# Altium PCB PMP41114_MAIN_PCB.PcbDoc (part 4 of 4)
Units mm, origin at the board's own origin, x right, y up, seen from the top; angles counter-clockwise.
Board outline 159.1 x 70 mm, 6 copper layers (Top Layer, Signal Layer 1, Signal Layer 2, Signal Layer 3, Signal Layer 4, Bottom Layer), stack 1.671 mm thick; 188 components, 146 nets, 720 pads, 326 vias.
Unrouted connection lines stored in the file: 209.
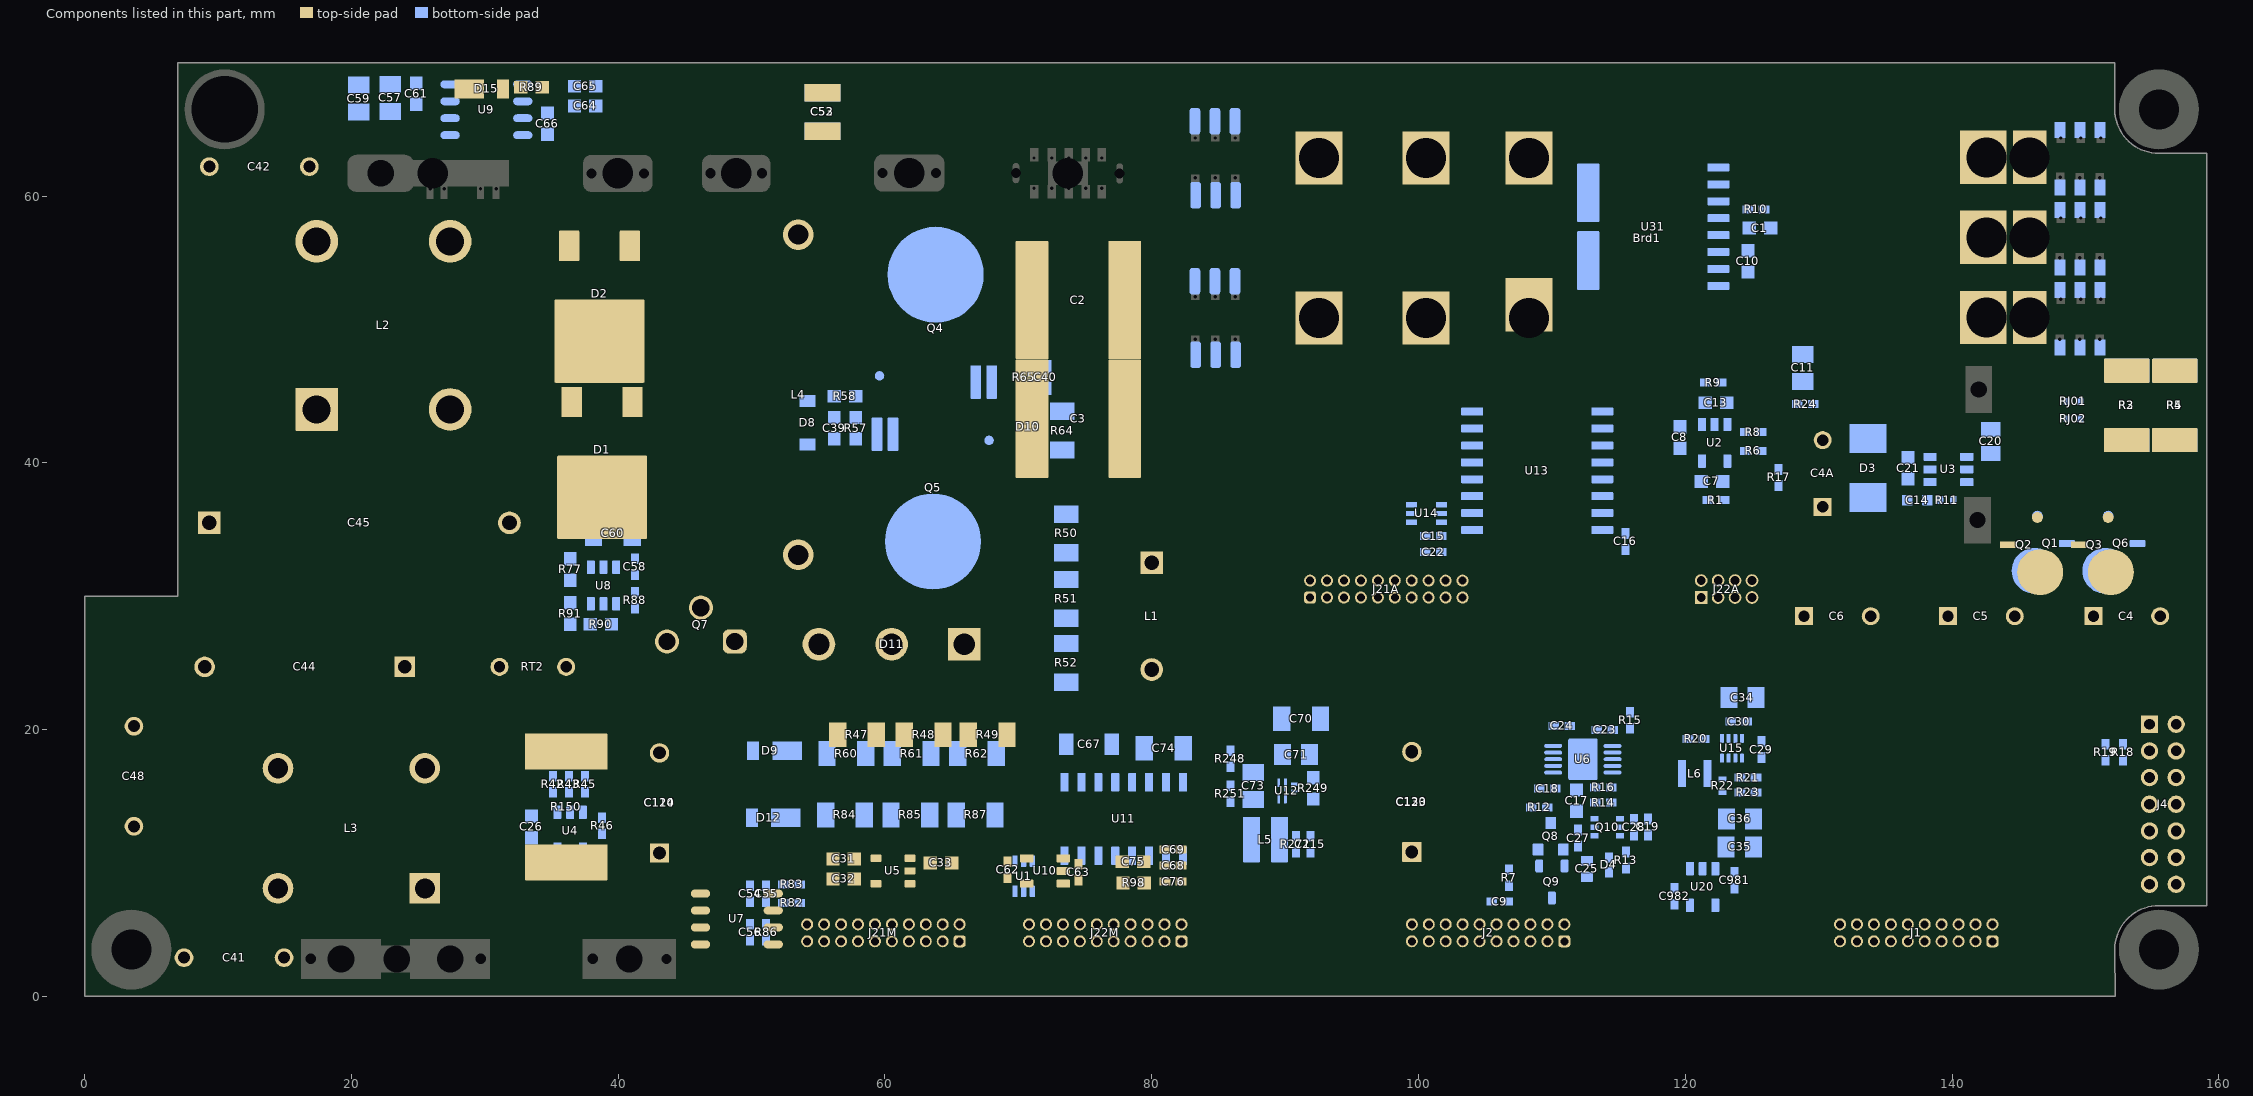
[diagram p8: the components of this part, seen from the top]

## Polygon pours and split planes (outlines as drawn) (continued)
Lout on Signal Layer 1 "SIGNAL_LAYER_1_LOUT_P439" (solid, remove dead copper, pour order 439): 11.7,7.7 13.3,9.3 20,9.3 24.8,4.5 30.4,4.5 30.4,1.6 29.5,0.7 12.9,0.7 11.7,1.9
Vbulk1 on Signal Layer 1 "SIGNAL_LAYER_1_VBULK1_P427" (solid, remove dead copper, pour order 427): 65.9,64.1 66.9,63.1 66.9,58.3 65.7,57.1 59.4,57.1 58.6,57.9 58.6,62.9 59.8,64.1
PGND on Signal Layer 1 "SIGNAL_LAYER_1_PGND_P420" (solid, remove dead copper, pour order 420): 73.4,59.8 73.975,59.225 78.475,59.225 78.7,59.45 78.7,63.925 76.225,63.925 75.775,63.475 75.775,61.425 75.175,60.825 73.55,60.825 73.4,60.675
SGND-1 on Bottom Layer "BOTTOM_LAYER_SGND-1_P561" (solid, remove dead copper, pour order 561): 144.3,69.1 147.4,69.1 147.4,48.7 147.4,47.5 144.3,47.5
PGND on Bottom Layer "BOTTOM_LAYER_PGND_P547" (solid, remove dead copper, pour order 547): 89.664,67.151 95.164,67.151 95.764,66.551 95.764,46.251 89.664,46.251
VBB on Bottom Layer "BOTTOM_LAYER_VBB_P546" (solid, remove dead copper, pour order 546): 97.4,67.3 102.9,67.3 103.5,66.7 103.5,46.4 97.4,46.4
54Vout-1 on Bottom Layer "BOTTOM_LAYER_54VOUT-1_P395" (solid, remove dead copper, pour order 395): 18 vertices, not listed, extent 128.2,10.7 157.3,38.6
PE on Bottom Layer "BOTTOM_LAYER_PE_P528" (solid, remove dead copper, pour order 528): 7.6,62.9 9,61.5 10.8,61.5 16.2,66.9 16.2,69.4 16,69.6 8.2,69.6 7.6,69
Lout on Bottom Layer "BOTTOM_LAYER_LOUT_P529" (solid, remove dead copper, pour order 529): 17.9,9.4 22.3,5 29.7,5 30.5,4.2 30.5,1.3 30.1,0.9 18.7,0.9 15.7,3.9 13.3,6.3 13.3,8.8 13.9,9.4
PE on Bottom Layer "BOTTOM_LAYER_PE_P523" (solid, remove dead copper, pour order 523): 7.2,0.5 8.2,1.5 8.2,12.4 6.7,13.9 1.5,13.9 0.6,13 0.6,2.1 0.7,2.1 2.3,0.5 0.7,2.1 2.3,0.5
ZCD on Bottom Layer "BOTTOM_LAYER_ZCD_P507" (solid, pour order 507): 47.7,65.5 36.8,65.5 34.5,63.2 34.5,60.3 34.6,60.2 34.8,60.2 34.9,60.3 34.9,63.1 36.7,64.9 46.7,64.9 46.8,65
VBB on Bottom Layer "BOTTOM_LAYER_VBB_P500" (solid, remove dead copper, pour order 500): 58.3,25.7 58.3,38.2 68.4,38.2 68.7,37.9 68.7,30 67.9,29.2 63.1,29.2 62.4,28.5 62.4,25.5 61.5,24.6 59.4,24.6
NetBrd1_S8 on Bottom Layer "BOTTOM_LAYER_NETBRD1_S8_P491" (solid, remove dead copper, pour order 491): 143.7,66.21 143.8,66.11 143.8,45.91 142.5,44.61 140.3,44.61 139.7,45.21 139.7,66.01 139.9,66.21
Line on Bottom Layer "BOTTOM_LAYER_LINE_P431" (solid, remove dead copper, pour order 431): 23 vertices, not listed, extent 25.6,29.7 55.1,57.9
NetC41_2 on Bottom Layer "BOTTOM_LAYER_NETC41_2_P465" (solid, remove dead copper, pour order 465): 8.1,17.8 12.1,13.8 19.1,13.8 19.1,52.7 18.1,53.7 10.3,53.7 8.1,51.5
NetC44_1 on Bottom Layer "BOTTOM_LAYER_NETC44_1_P459" (solid, remove dead copper, pour order 459): 24.088,46.9 28.156,46.9 29.4,45.573 29.4,29.4 27,27 27,13.6 25.9,12.5 23.4,12.5 22.2,13.7 22.2,43.843
Nout on Bottom Layer "BOTTOM_LAYER_NOUT_P450" (solid, remove dead copper, pour order 450): 43,8 46.4,8 46.6,7.8 46.6,6.1 46.3,5.8 42.8,5.8 42.5,6.1 42.5,7.5
N on Bottom Layer "BOTTOM_LAYER_N_P445" (solid, remove dead copper, pour order 445): 37.3,4.3 38.5,5.5 45.7,5.5 46.7,4.5 46.7,1.2 46.3,0.8 37.9,0.8 37.3,1.4
PGND on Bottom Layer "BOTTOM_LAYER_PGND_P444" (solid, remove dead copper, pour order 444): 39.6,8.3 41.3,10 43.8,10 43.8,11.6 42.4,13 40.8,13 38.1,10.3 33.6,10.3 33,9.7 33,9 33.7,8.3
Vbulk1 on Bottom Layer "BOTTOM_LAYER_VBULK1_P432" (solid, remove dead copper, pour order 432): 52.7,68.9 53.2,69.4 66,69.4 66.9,68.5 66.9,60.4 69.7,57.6 69.7,49.8 69.4,49.5 58.7,49.5 58.1,50.1 58.1,66.4 57.4,67.1 53.2,67.1 52.7,67.6
ZCD on Bottom Layer "BOTTOM_LAYER_ZCD_P424" (solid, remove dead copper, pour order 424): 46.1,60.9 46.7,60.3 55.8,60.3 56.7,61.2 56.7,65.5 46.7,65.5 46.1,64.9
Vbulk on Bottom Layer "BOTTOM_LAYER_VBULK_P421" (solid, remove dead copper, pour order 421): 67.1,47.4 67.3,47.2 67.3,44.2 67.5,44 68.1,44 68.4,43.7 68.4,40.9 60.3,40.9 60.2,41 60.2,43.8 60.1,43.9 59,43.9 58.7,44.2 58.7,47.4
Vbulk1 on Bottom Layer "BOTTOM_LAYER_VBULK1_P419" (solid, remove dead copper, pour order 419): 65.9,64.1 66.9,63.1 66.9,59.9 68.9,57.9 68.9,49.9 68.5,49.5 58.6,49.5 58.6,62.9 59.8,64.1
MID-1 on Bottom Layer "BOTTOM_LAYER_MID-1_P409" (solid, remove dead copper, pour order 409): 105.899,57.715 113.5,57.715 113.5,50.455 109.67,47 106,47 105.199,47.801 105.199,57.015
MID-2 on Bottom Layer "BOTTOM_LAYER_MID-2_P408" (solid, remove dead copper, pour order 408): 105.8,67.4 113.8,67.4 113.8,58 105.9,58 105.1,58.8 105.1,66.7
SGND on Bottom Layer "BOTTOM_LAYER_SGND_P398" (solid, remove dead copper, pour order 398): 150.1,47.786 151.857,47.786 151.857,62.1 158.5,62.1 158.5,45.4 157.9,44.8 151,44.8 150.1,45.7
SGND-1 on Bottom Layer "BOTTOM_LAYER_SGND-1_P397" (solid, remove dead copper, pour order 397): 151.7,40.7 151.1,41.3 151.1,43.3 151.7,43.9 158.2,43.9 158.5,43.6 158.5,40.7 151.8,40.7
54Vout on Bottom Layer "BOTTOM_LAYER_54VOUT_P396" (solid, remove dead copper, pour order 396): 144.3,35.5 157.6,35.5 158.4,36.3 158.4,39.7 157.8,40.3 144.8,40.3 144.1,39.6 144.1,35.7
NetBrd1_S8 on Bottom Layer "BOTTOM_LAYER_NETBRD1_S8_P393" (solid, remove dead copper, pour order 393): 143.7,69.2 143.9,69 143.9,44.2 143.2,43.5 134.6,43.5 130.8,43.5 127.7,46.6 127.7,66.6 130.3,69.2
PGND on Bottom Layer "BOTTOM_LAYER_PGND_P248" (solid, remove dead copper, pour order 248): 73.391,59.807 73.941,59.257 78.491,59.257 78.691,59.457 78.691,63.932 76.216,63.932 75.766,63.482 75.766,61.432 75.459,61.125 73.7,61.125 73.391,60.816
ZCD on Bottom Layer "ZCD" (solid, remove dead copper, pour order 388): 21 vertices, not listed, extent 30.75,58.75 39.75,69.25
Neutral on Bottom Layer "Neutral" (solid, remove dead copper, pour order 390): 20,66.75 19.75,66.5 19.75,65.5 20,65.25 26.5,65.25 26.75,65.5 28,65.5 28.25,65.75 28.25,66 28,66.25 26,66.25 25.25,67 20,67 19.75,66.75
VBB on Signal Layer 4 "SIGNAL_LAYER_4_VBB_P496" (solid, remove dead copper, pour order 496): 70.7,49.1 79.8,40 100,40 104.8,44.8 104.8,54.5 104.8,65.3 102.8,67.3 81.32,67.3 81.32,59.72 80.1,58.5 71.9,58.5 70.7,57.3 70.7,57.2
12VSB on Signal Layer 4 "Signal Layer 4-12VSB" (solid, remove dead copper, pour order 574): 116.9,1.5 152.6,1.5 158.5,7.4 158.5,22.3 129.3,22.3 125.4,26.2 125.4,44.1 123.147,44.1 116.9,37.767 116.9,23.231
AGND on Signal Layer 4 "SIGNAL_LAYER_4_AGND_P569" (solid, remove dead copper, pour order 569): 98,3.5 98,6.2 99.2,7.4 102.6,7.4 110.198,14.998 110.198,18.121 113,20.924 113,37.479 123.8,48.279 123.8,57.4 125,57.4 125,47.834 115.4,38.234 115.4,12.4 106.5,3.5
ZCD on Signal Layer 4 "SIGNAL_LAYER_4_ZCD_P566" (solid, remove dead copper, pour order 566): 46.275,60.725 46.675,60.325 51.075,60.325 51.375,60.625 51.375,64.025 49.475,65.925 35.075,65.925 32.775,63.625 32.775,59.725 33.375,59.125 34.175,59.125 34.175,64.225 35.475,65.525 45.875,65.525 46.275,65.125
SGND-1 on Signal Layer 4 "SIGNAL_LAYER_4_SGND-1_P559" (solid, remove dead copper, pour order 559): 126.1,65.3 126.1,26.5 129.5,23.1 158.5,23.1 158.5,69.2 130,69.2
PE on Signal Layer 4 "SIGNAL_LAYER_4_PE_P534" (solid, remove dead copper, pour order 534): 7.6,62.9 9,61.5 10.8,61.5 16.2,66.9 16.2,69.4 16,69.6 8.2,69.6 7.6,69
Lout on Signal Layer 4 "SIGNAL_LAYER_4_LOUT_P525" (solid, remove dead copper, pour order 525): 11.7,7.7 13.3,9.3 20,9.3 24.8,4.5 30.4,4.5 30.4,1.6 29.5,0.7 12.9,0.7 11.7,1.9
PE on Signal Layer 4 "SIGNAL_LAYER_4_PE_P524" (solid, remove dead copper, pour order 524): 7.2,0.5 8.2,1.5 8.2,11.3 5.8,13.7 1.3,13.7 0.6,13 0.6,2.1 0.7,2.1 2.3,0.5 0.7,2.1 2.3,0.5
Vbulk on Signal Layer 4 "SIGNAL_LAYER_4_VBULK_P470" (solid, remove dead copper, pour order 470): 41.4,16.6 41.4,18.1 56.1,32.8 56.1,45.1 59.9,48.9 70.2,48.9 101.1,18 101.1,16.4 100.4,15.7 42.3,15.7
ZCD on Signal Layer 4 "SIGNAL_LAYER_4_ZCD_P425" (solid, remove dead copper, pour order 425): 19 vertices, not listed, extent 33.1,19.6 55.2,65
Vbulk1 on Signal Layer 4 "SIGNAL_LAYER_4_VBULK1_P480" (solid, remove dead copper, pour order 480): 58.5,63.4 66.7,63.4 66.7,58.1 66.2,57.6 59.5,57.6 58.5,58.6
Line on Signal Layer 4 "SIGNAL_LAYER_4_LINE_P475" (solid, remove dead copper, pour order 475): 25.6,57 26.5,57.9 28.4,57.9 33,53.3 33,40.6 33,34.9 32.4,34.3 30.8,34.3 29.8,35.3 29.8,45.9 25.6,50.1
NetC41_2 on Signal Layer 4 "SIGNAL_LAYER_4_NETC41_2_P466" (solid, remove dead copper, pour order 466): 8.1,19.1 12,15.2 17.1,15.2 19.9,18 19.9,51.9 18.1,53.7 13.5,53.7 8.1,48.3
NetC44_1 on Signal Layer 4 "SIGNAL_LAYER_4_NETC44_1_P458" (solid, remove dead copper, pour order 458): 22.95,46.9 27.956,46.9 29.7,45.04 29.7,26.3 28.9,25.5 28.9,15.5 25.9,12.5 23.4,12.5 21.3,14.6 21.3,44.229
N on Signal Layer 4 "SIGNAL_LAYER_4_N_P446" (solid, remove dead copper, pour order 446): 37.3,4.3 38.3,5.3 45.9,5.3 46.7,4.5 46.7,1.2 46.3,0.8 37.9,0.8 37.3,1.4
Nout on Signal Layer 4 "SIGNAL_LAYER_4_NOUT_P438" (solid, remove dead copper, pour order 438): 24.7,10.6 29.3,10.6 31.9,8 46.4,8 47.1,7.3 47.1,6.2 46.4,5.5 25,5.5 23,7.5 23,8.9
PGND on Signal Layer 4 "SIGNAL_LAYER_4_PGND_P429" (solid, remove dead copper, pour order 429): 33.4,13.8 98.6,13.8 100.2,12.2 100.2,10.1 99.5,9.4 83.997,9.4 83.4,8.949 83.4,7.3 82.8,6.7 49.1,6.7 47.1,8.7 33.4,8.7
PGND on Signal Layer 4 "SIGNAL_LAYER_4_PGND_P222" (solid, remove dead copper, pour order 222): 76.3,64 78.5,64 78.75,63.75 78.75,59.5 78.5,59.25 73.95,59.25 73.4,59.8 73.4,60.675 73.55,60.825 75.175,60.825 75.775,61.425 75.775,63.475
12VS on Signal Layer 3 "Signal Layer 3-12VS" (solid, remove dead copper, pour order 573): 17 vertices, not listed, extent 92.4,0.8 158.5,45.6
SGND-1 on Signal Layer 3 "SIGNAL_LAYER_3_SGND-1_P563" (solid, remove dead copper, pour order 563): 127.9,69.2 127.9,23.8 129.7,22 158.5,22 158.5,69.2
VBB on Signal Layer 3 "SIGNAL_LAYER_3_VBB_P545" (solid, remove dead copper, pour order 545): 97.4,67.3 102.9,67.3 104.5,65.7 104.5,54.8 104.5,46.7 104.2,46.4 98.835,46.4 97.4,47.834
SGND-1 on Signal Layer 3 "SIGNAL_LAYER_3_SGND-1_P542" (solid, remove dead copper, pour order 542): 144.3,69.1 144.3,41.856 147.456,38.7 158.6,38.7 158.6,44.3 151.2,44.3 151.2,48.7 147.4,48.7 147.4,69.1
PE on Signal Layer 3 "SIGNAL_LAYER_3_PE_P533" (solid, remove dead copper, pour order 533): 7.6,62.9 9,61.5 10.8,61.5 16.2,66.9 16.2,69.4 16,69.6 8.2,69.6 7.6,69
Lout on Signal Layer 3 "SIGNAL_LAYER_3_LOUT_P527" (solid, remove dead copper, pour order 527): 11.7,7.7 13.3,9.3 20,9.3 24.8,4.5 30.4,4.5 30.4,1.6 29.5,0.7 12.9,0.7 11.7,1.9
PE on Signal Layer 3 "SIGNAL_LAYER_3_PE_P521" (solid, remove dead copper, pour order 521): 7.2,0.5 8.2,1.5 8.2,12.4 6.7,13.9 1.5,13.9 0.6,13 0.6,2.1 0.7,2.1 2.3,0.5 0.7,2.1 2.3,0.5
ZCD on Signal Layer 3 "SIGNAL_LAYER_3_ZCD_P510" (solid, remove dead copper, pour order 510): 46.3,60.7 46.7,60.3 51.1,60.3 51.4,60.6 51.4,64 49.5,65.9 35.1,65.9 32.8,63.6 32.8,59.7 33.4,59.1 34.2,59.1 34.2,64.2 35.5,65.5 45.9,65.5 46.3,65.1
PGND on Signal Layer 3 "SIGNAL_LAYER_3_PGND_P508" (solid, remove dead copper, pour order 508): 43.958,27.5 45.937,25.9 48.9,25.9 52.3,22.5 74.6,22.5 74.6,6.5 63.6,6.5 49.5,20.6 42.5,20.6 40.7,22.4 40.7,26.1 42.1,27.5
NetD11_1 on Signal Layer 3 "SIGNAL_LAYER_3_NETD11_1_P499" (solid, remove dead copper, pour order 499): 45.3,30.3 45.6,30.6 66.2,30.6 67.8,29 67.8,23.5 52.8,23.5 51.5,24.8 51.5,27.8 50.4,28.9 47.557,28.9 46.957,28.2 45.6,28.2 45.3,28.5
PGND on Signal Layer 3 "SIGNAL_LAYER_3_NONET_P484" (solid, remove dead copper, pour order 498): 96.1,69.4 96.1,53.5 96.1,47.377 104.7,38.777 104.7,23.5 102.8,21.6 102.8,12.7 99.9,9.8 72.7,9.8 70.3,12.2 70.3,63.8 75.9,69.4
PGND on Signal Layer 3 "SIGNAL_LAYER_3_PGND_P487" (solid, remove dead copper, pour order 487): 33.8,8.9 46,8.9 46.8,9.7 46.8,11 46.2,11.6 35.5,11.6 33.6,9.7 33.6,9.1
SWNODE on Signal Layer 3 "SIGNAL_LAYER_3_SWNODE_P482" (solid, remove dead copper, pour order 482): 43,63.2 44.2,62 44.2,60.5 45.1,59.6 55.4,59.6 57.6,57.4 57.6,53.9 57.5,53.9 56.8,53.2 38.6,53.2 37.3,54.5 37.3,62.9 37.6,63.2
Line on Signal Layer 3 "SIGNAL_LAYER_3_LINE_P476" (solid, remove dead copper, pour order 476): 23 vertices, not listed, extent 25.6,31.9 54.8,57.9
Neutral on Signal Layer 3 "SIGNAL_LAYER_3_NEUTRAL_P474" (solid, remove dead copper, pour order 474): 8.1,48.5 17.5,48.5 24.5,55.5 24.5,65.1 23.6,66 18,66 8.1,56.1
NetC41_2 on Signal Layer 3 "SIGNAL_LAYER_3_NETC41_2_P457" (solid, remove dead copper, pour order 457): 8.1,17.8 12.1,13.8 19.1,13.8 19.9,14.6 19.9,47 8.1,47
NetC44_1 on Signal Layer 3 "SIGNAL_LAYER_3_NETC44_1_P468" (solid, remove dead copper, pour order 468): 24.088,46.9 28.156,46.9 29.7,45.253 29.7,26.3 28.9,25.5 28.9,17.3 27.4,15.8 22.8,15.8 21.3,17.3 21.3,42.386
N on Signal Layer 3 "SIGNAL_LAYER_3_N_P456" (solid, remove dead copper, pour order 456): 37.3,4.3 38.3,5.3 45.9,5.3 46.7,4.5 46.7,1.2 46.3,0.8 37.9,0.8 37.3,1.4
Nout on Signal Layer 3 "SIGNAL_LAYER_3_NOUT_P447" (solid, remove dead copper, pour order 447): 24.7,10.6 29.3,10.6 31.9,8 46.4,8 47.1,7.3 47.1,6.2 46.4,5.5 25,5.5 23,7.5 23,8.9
PGND on Signal Layer 3 "SIGNAL_LAYER_3_PGND_P441" (solid, remove dead copper, pour order 441): 73.391,59.807 73.941,59.257 78.491,59.257 78.691,59.457 78.691,63.932 76.216,63.932 75.766,63.482 75.766,61.432 75.166,60.832 73.541,60.832 73.391,60.682
54Vout on Signal Layer 2 "SIGNAL_LAYER_2_54VOUT_P576" (solid, remove dead copper, pour order 576): 142.988,34.5 142.988,37.412 148.047,42.47 158.362,42.321 158.362,34.5
54Vout-1 on Signal Layer 2 "SIGNAL_LAYER_2_54VOUT-1_P565" (solid, remove dead copper, pour order 565): 126.5,39.6 143.6,39.6 148.7,34.5 158.1,34.5 158.1,22.1 155.7,19.7 129.4,19.7 125.5,23.6 125.5,38.6
SGND on Signal Layer 2 "Signal Layer 2-SGND" (solid, remove dead copper, pour order 572): 18 vertices, not listed, extent 92.4,0.8 158.5,63.2
NetBrd1_S8 on Signal Layer 2 "SIGNAL_LAYER_2_NETBRD1_S8_P557" (solid, remove dead copper, pour order 557): 147,69.2 147,40.3 126.9,40.3 124.8,42.4 124.8,63.6 130.4,69.2
VBB on Signal Layer 2 "SIGNAL_LAYER_2_VBB_P411" (solid, remove dead copper, pour order 411): 97.4,67.3 102.9,67.3 104.5,65.7 104.5,54.8 104.5,46.7 104.2,46.4 97.4,46.4
PGND on Signal Layer 2 "SIGNAL_LAYER_2_PGND_P544" (solid, remove dead copper, pour order 544): 90,67.3 94.883,67.3 96.483,65.7 96.483,54.8 96.483,46.7 96.183,46.4 90.96,46.4 90,47.36
PE on Signal Layer 2 "SIGNAL_LAYER_2_PE_P532" (solid, remove dead copper, pour order 532): 7.6,62.9 9,61.5 10.8,61.5 16.2,66.9 16.2,69.4 16,69.6 8.2,69.6 7.6,69
PE on Signal Layer 2 "SIGNAL_LAYER_2_PE_P522" (solid, remove dead copper, pour order 522): 7.2,0.5 8.2,1.5 8.2,12.4 6.7,13.9 1.5,13.9 0.6,13 0.6,2.1 0.7,2.1 2.3,0.5 0.7,2.1 2.3,0.5
SGND on Signal Layer 2 "SIGNAL_LAYER_2_SGND_P516" (solid, remove dead copper, pour order 516): 114.2,14.8 117.3,14.8 127.5,4.6 131.9,4.6 132.1,4.4 132.1,2.3 130.6,0.8 113.6,0.8 112.9,1.5 112.9,13.5
PGND on Signal Layer 2 "SIGNAL_LAYER_2_PGND_P513" (solid, remove dead copper, pour order 513): 89.4,10.6 89.4,18.4 95.1,24.1 95.1,31.5 100.9,31.5 100.9,10.8 99.8,9.7 90.3,9.7
SGND on Signal Layer 2 "SIGNAL_LAYER_2_SGND_P511" (solid, remove dead copper, pour order 511): 151.5,62.1 158,62.1 158,44.997 157.503,44.5 151.5,44.5
Vbulk1 on Signal Layer 2 "SIGNAL_LAYER_2_VBULK1_P502" (solid, remove dead copper, pour order 502): 65.9,64.1 66.9,63.1 66.9,58.3 65.7,57.1 59.4,57.1 58.6,57.9 58.6,62.9 59.8,64.1
PGND on Signal Layer 2 "SIGNAL_LAYER_2_PGND_P481" (solid, remove dead copper, pour order 481): 33.8,8.9 44.2,8.9 44.6,9.3 44.6,11.2 44.2,11.6 35.5,11.6 33.6,9.7 33.6,9.1
ZCD on Signal Layer 2 "SIGNAL_LAYER_2_ZCD_P478" (solid, remove dead copper, pour order 478): 22 vertices, not listed, extent 34.6,55.4 51.6,69.2
SWNODE on Signal Layer 2 "SIGNAL_LAYER_2_SWNODE_P426" (solid, remove dead copper, pour order 426): 43,63.2 44.2,62 44.2,60.5 45.1,59.6 55.4,59.6 56.7,58.3 56.7,56.2 55.9,55.4 42.6,55.4 37.3,60.7 37.3,62.9 37.6,63.2
Vbulk on Signal Layer 2 "SIGNAL_LAYER_2_VBULK_P471" (solid, remove dead copper, pour order 471): 39.6,49 42.7,52.1 67.9,52.1 69.9,50.1 69.9,37.3 66.5,33.9 66.5,19.6 62.8,15.9 42.9,15.9 39.6,19.2
NetC41_2 on Signal Layer 2 "SIGNAL_LAYER_2_NETC41_2_P463" (solid, remove dead copper, pour order 463): 19.3,45.6 19.6,45.3 19.5,45.2 19.5,10.9 19.3,10.7 12.5,10.7 11.9,11.3 11.9,31.2 12.1,31.2 14.3,33.4 14.3,44 15.9,45.6
Neutral on Signal Layer 2 "SIGNAL_LAYER_2_NEUTRAL_P462" (solid, remove dead copper, pour order 462): 8.1,33.7 8.2,33.6 12.9,33.6 13,33.7 13,44 24.5,55.5 24.5,65.1 23.6,66 18,66 8.1,56.1
NetC44_1 on Signal Layer 2 "SIGNAL_LAYER_2_NETC44_1_P460" (solid, remove dead copper, pour order 460): 24.088,46.9 28.156,46.9 29.7,45.253 29.7,26.3 28.9,25.5 28.9,15.5 25.9,12.5 23.4,12.5 21.3,14.6 21.3,42.386
N on Signal Layer 2 "SIGNAL_LAYER_2_N_P448" (solid, remove dead copper, pour order 448): 37.3,4.3 38.3,5.3 45.9,5.3 46.7,4.5 46.7,1.2 46.3,0.8 37.9,0.8 37.3,1.4
Nout on Signal Layer 2 "SIGNAL_LAYER_2_NOUT_P440" (solid, remove dead copper, pour order 440): 23.3,11.4 28.5,11.4 31.9,8 46.4,8 47.1,7.3 47.1,6.2 46.4,5.5 25.3,5.5 22.5,8.3 22.5,10.6
Lout on Signal Layer 2 "SIGNAL_LAYER_2_LOUT_P434" (solid, remove dead copper, pour order 434): 11.7,7.7 13.3,9.3 20,9.3 24.8,4.5 30.4,4.5 30.4,1.6 29.5,0.7 12.9,0.7 11.7,1.9
PGND on Signal Layer 2 "SIGNAL_LAYER_2_PGND_P234" (solid, remove dead copper, pour order 234): 73.4,59.25 78.6,59.25 78.6,63.925 76.225,63.925 75.775,63.475 75.775,61.425 75.175,60.825 73.55,60.825 73.4,60.675

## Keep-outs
Top Layer:
  lines w0.254: 83.5,48.2 85.8,48.2 ; 83.7,53.6 86,53.6
Signal Layer 4:
  lines w0.254: 78.784,31.3 78.784,33.7 81.154,33.7 81.154,31.3 78.784,31.3
Keep-Out Layer:
  text ".Layer_Name" at -10.544,-45.406 h1.52

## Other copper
Top Layer:
  pour cut-out: 58.515,26.4 ccw(c60.5,26.4) 60.5,24.415 ccw(c60.5,26.4) 62.485,26.4 ccw(c60.5,26.4) 60.5,28.385 ccw(c60.5,26.4)
Signal Layer 1:
  pour cut-out: 99.454,17.025 cw(c99.454,18.329) 98.151,18.329 cw(c99.454,18.329) 99.454,19.633 cw(c99.454,18.329) 100.758,18.329 cw(c99.454,18.329)
  pour cut-out: 64.181,26.4 ccw(c65.95,26.4) 65.95,24.631 ccw(c65.95,26.4) 67.719,26.4 ccw(c65.95,26.4) 65.95,28.169 ccw(c65.95,26.4)
  pour cut-out: 53.281,26.4 ccw(c55.05,26.4) 55.05,24.631 ccw(c55.05,26.4) 56.819,26.4 ccw(c55.05,26.4) 55.05,28.169 ccw(c55.05,26.4)
  pour cut-out: 79.954,23.175 cw(c79.954,24.479) 78.651,24.479 cw(c79.954,24.479) 79.954,25.783 cw(c79.954,24.479) 81.258,24.479 cw(c79.954,24.479)
  pour cut-out: 58.731,26.4 ccw(c60.5,26.4) 60.5,24.631 ccw(c60.5,26.4) 62.269,26.4 ccw(c60.5,26.4) 60.5,28.169 ccw(c60.5,26.4)
  pour cut-out: 53.2,29.094 cw(c53.2,30.4) 51.894,30.4 cw(c53.2,30.4) 53.2,31.706 cw(c53.2,30.4) 54.506,30.4 cw(c53.2,30.4)
  pour cut-out: 52.068,33.1 ccw(c53.5,33.1) 53.5,31.668 ccw(c53.5,33.1) 54.932,33.1 ccw(c53.5,33.1) 53.5,34.532 ccw(c53.5,33.1)
  pour cut-out: 55.825,40.263 cw(c55.825,40.675) 55.413,40.675 cw(c55.825,40.675) 55.825,41.087 cw(c55.825,40.675) 56.237,40.675 cw(c55.825,40.675)
  pour cut-out: 36.054,23.375 cw(c36.054,24.679) 34.751,24.679 cw(c36.054,24.679) 36.054,25.983 cw(c36.054,24.679) 37.358,24.679 cw(c36.054,24.679)
  pour cut-out: 46.202,27.853 cw(c46.202,29.157) 44.898,29.157 cw(c46.202,29.157) 46.202,30.461 cw(c46.202,29.157) 47.506,29.157 cw(c46.202,29.157)
  pour cut-out: 82.54,65.78 87.04,65.78 87.04,60.08 82.54,60.08
  pour cut-out: 82.54,53.65 87.04,53.65 87.04,47.95 82.54,47.95
  pour cut-out: 134.08,28.76 139.774,34.454 140.57,34.449 140.57,34.18 139.8,34.18 134.38,28.76
  pour cut-out: 143.002,37.402 151.474,45.874 152.074,45.87 152.075,45.6 151.5,45.6 143.302,37.402
  pour cut-out: 71.6,48.5 71.6,54.3 72.2,54.9 73.2,54.9 73.7,54.4 73.7,48.5
  pour cut-out: 61,38.5 67.2,38.5 67.8,37.9 67.8,35.7 67.1,35 61.1,35 60.4,35.7 60.4,37.9
  pour cut-out: 61,44.9 67.2,44.9 67.8,44.3 67.8,43.3 67.3,42.8 60.9,42.8 60.4,43.3 60.4,44.3
  pour cut-out: 44.4,10.1 44.4,9.7 85.95,9.7 89.915,5.961 90.283,6.129 86.209,10.1
  pour cut-out: 80.655,64.205 80.655,64.805 80.555,64.905 79.955,64.905 79.855,64.805 79.855,64.205 79.955,64.105 80.555,64.105
  pour cut-out: 102.8,30.45 103.9,30.45 103.9,29.35 102.8,29.35
  pour cut-out: 102.8,30.45 103.9,30.45 103.9,29.35 102.8,29.35
  pour cut-out: 94.3,20.5 94.3,21.1 94.2,21.2 93.6,21.2 93.5,21.1 93.5,20.5 93.6,20.4 94.2,20.4
  pour cut-out: 87.3,18.6 87.3,19.2 87.2,19.3 86.6,19.3 86.5,19.2 86.5,18.6 86.6,18.5 87.2,18.5
  pour cut-out: 100.173,29.667 100.173,31.567 99.852,31.888 95.394,31.888 95.094,31.588 95.094,29.6 95.394,29.3 99.806,29.3
  pour cut-out: 70.9,10.8 70.9,11.4 70.8,11.5 70.2,11.5 70.1,11.4 70.1,10.8 70.2,10.7 70.8,10.7
Signal Layer 2:
  pour cut-out: 97.731,18.3 ccw(c99.5,18.3) 99.5,16.531 ccw(c99.5,18.3) 101.269,18.3 ccw(c99.5,18.3) 99.5,20.069 ccw(c99.5,18.3)
  pour cut-out: 52.068,33.1 ccw(c53.5,33.1) 53.5,31.668 ccw(c53.5,33.1) 54.932,33.1 ccw(c53.5,33.1) 53.5,34.532 ccw(c53.5,33.1)
  pour cut-out: 53.234,26.481 ccw(c55.003,26.481) 55.003,24.712 ccw(c55.003,26.481) 56.773,26.481 ccw(c55.003,26.481) 55.003,28.25 ccw(c55.003,26.481)
  pour cut-out: 53.2,29.094 cw(c53.2,30.4) 51.894,30.4 cw(c53.2,30.4) 53.2,31.706 cw(c53.2,30.4) 54.506,30.4 cw(c53.2,30.4)
  pour cut-out: 41.388,25.371 cw(c41.388,26.677) 40.082,26.677 cw(c41.388,26.677) 41.388,27.983 cw(c41.388,26.677) 42.694,26.677 cw(c41.388,26.677)
  pour cut-out: 40.4,25.594 cw(c40.4,26.9) 39.094,26.9 cw(c40.4,26.9) 40.4,28.206 cw(c40.4,26.9) 41.706,26.9 cw(c40.4,26.9)
  pour cut-out: 48.74,25.294 cw(c48.74,26.6) 47.434,26.6 cw(c48.74,26.6) 48.74,27.906 cw(c48.74,26.6) 50.046,26.6 cw(c48.74,26.6)
  pour cut-out: 43.66,25.294 cw(c43.66,26.6) 42.354,26.6 cw(c43.66,26.6) 43.66,27.906 cw(c43.66,26.6) 44.966,26.6 cw(c43.66,26.6)
  pour cut-out: 46.2,27.834 cw(c46.2,29.14) 44.894,29.14 cw(c46.2,29.14) 46.2,30.446 cw(c46.2,29.14) 47.506,29.14 cw(c46.2,29.14)
  pour cut-out: 61,38.5 67.2,38.5 67.8,37.9 67.8,35.7 67.1,35 61.1,35 60.4,35.7 60.4,37.9
  pour cut-out: 67.5,27.9 67.3,28.1 64.6,28.1 64.2,27.7 64.2,25.1 64.6,24.7 67.5,24.7
  pour cut-out: 94.3,20.5 94.3,21.1 94.2,21.2 93.6,21.2 93.5,21.1 93.5,20.5 93.6,20.4 94.2,20.4
Signal Layer 3:
  pour cut-out: 99.454,16.975 cw(c99.454,18.279) 98.151,18.279 cw(c99.454,18.279) 99.454,19.583 cw(c99.454,18.279) 100.758,18.279 cw(c99.454,18.279)
  pour cut-out: 79.954,23.175 cw(c79.954,24.479) 78.651,24.479 cw(c79.954,24.479) 79.954,25.783 cw(c79.954,24.479) 81.258,24.479 cw(c79.954,24.479)
  pour cut-out: 58.731,26.4 ccw(c60.5,26.4) 60.5,24.631 ccw(c60.5,26.4) 62.269,26.4 ccw(c60.5,26.4) 60.5,28.169 ccw(c60.5,26.4)
  pour cut-out: 52.137,30.4 ccw(c53.2,30.4) 53.2,29.337 ccw(c53.2,30.4) 54.263,30.4 ccw(c53.2,30.4) 53.2,31.463 ccw(c53.2,30.4)
  pour cut-out: 82.54,65.78 87.04,65.78 87.04,60.08 82.54,60.08
  pour cut-out: 82.54,53.65 87.04,53.65 87.04,47.95 82.54,47.95
  pour cut-out: 134.08,28.76 139.774,34.454 140.57,34.449 140.57,34.18 139.8,34.18 134.38,28.76
  pour cut-out: 143.002,37.402 151.474,45.874 159.14,45.825 159.14,45.599 151.5,45.6 143.302,37.402
  pour cut-out: 94.3,20.5 94.3,21.1 94.2,21.2 93.6,21.2 93.5,21.1 93.5,20.5 93.6,20.4 94.2,20.4
  pour cut-out: 72.2,48.6 73.3,48.6 73.6,48.9 73.6,53.937 73.137,54.4 72.3,54.4 71.811,53.911 71.811,48.989
  pour cut-out: 80.688,64.191 80.688,64.791 80.588,64.891 79.988,64.891 79.888,64.791 79.888,64.191 79.988,64.091 80.588,64.091
  pour cut-out: 102.7,30.45 103.8,30.45 103.8,29.35 102.7,29.35
  pour cut-out: 87.3,18.6 87.3,19.2 87.2,19.3 86.6,19.3 86.5,19.2 86.5,18.6 86.6,18.5 87.2,18.5
  pour cut-out: 100.173,29.667 100.173,31.567 99.852,31.888 95.394,31.888 95.094,31.588 95.094,29.6 95.394,29.3 99.806,29.3
  pour cut-out: 70.9,10.8 70.9,11.4 70.8,11.5 70.2,11.5 70.1,11.4 70.1,10.8 70.2,10.7 70.8,10.7
Signal Layer 4:
  pour cut-out: 93.3,20.8 ccw(c93.9,20.8) 93.9,20.2 ccw(c93.9,20.8) 94.5,20.8 ccw(c93.9,20.8) 93.9,21.4 ccw(c93.9,20.8)
  pour cut-out: 47.9,18.4 ccw(c48.5,18.4) 48.5,17.8 ccw(c48.5,18.4) 49.1,18.4 ccw(c48.5,18.4) 48.5,19 ccw(c48.5,18.4)
  pour cut-out: 96.1,40.1 ccw(c96.7,40.1) 96.7,39.5 ccw(c96.7,40.1) 97.3,40.1 ccw(c96.7,40.1) 96.7,40.7 ccw(c96.7,40.1)
  pour cut-out: 94.7,41.3 ccw(c95.3,41.3) 95.3,40.7 ccw(c95.3,41.3) 95.9,41.3 ccw(c95.3,41.3) 95.3,41.9 ccw(c95.3,41.3)
  pour cut-out: 97.4,43.8 ccw(c98,43.8) 98,43.2 ccw(c98,43.8) 98.6,43.8 ccw(c98,43.8) 98,44.4 ccw(c98,43.8)
  pour cut-out: 91.834,41.995 ccw(c92.434,41.995) 92.434,41.395 ccw(c92.434,41.995) 93.034,41.995 ccw(c92.434,41.995) 92.434,42.595 ccw(c92.434,41.995)
  pour cut-out: 67.3,19.8 ccw(c67.9,19.8) 67.9,19.2 ccw(c67.9,19.8) 68.5,19.8 ccw(c67.9,19.8) 67.9,20.4 ccw(c67.9,19.8)
  pour cut-out: 67.738,16.524 ccw(c68.338,16.524) 68.338,15.924 ccw(c68.338,16.524) 68.938,16.524 ccw(c68.338,16.524) 68.338,17.124 ccw(c68.338,16.524)
  pour cut-out: 74.338,17.124 ccw(c74.938,17.124) 74.938,16.524 ccw(c74.938,17.124) 75.538,17.124 ccw(c74.938,17.124) 74.938,17.724 ccw(c74.938,17.124)
  pour cut-out: 86.3,18.9 ccw(c86.9,18.9) 86.9,18.3 ccw(c86.9,18.9) 87.5,18.9 ccw(c86.9,18.9) 86.9,19.5 ccw(c86.9,18.9)
  pour cut-out: 77.1,20.5 ccw(c77.7,20.5) 77.7,19.9 ccw(c77.7,20.5) 78.3,20.5 ccw(c77.7,20.5) 77.7,21.1 ccw(c77.7,20.5)
  pour cut-out: 85.6,22 ccw(c86.2,22) 86.2,21.4 ccw(c86.2,22) 86.8,22 ccw(c86.2,22) 86.2,22.6 ccw(c86.2,22)
  pour cut-out: 53.2,29.094 cw(c53.2,30.4) 51.894,30.4 cw(c53.2,30.4) 53.2,31.706 cw(c53.2,30.4) 54.506,30.4 cw(c53.2,30.4)
  pour cut-out: 36.1,23.394 cw(c36.1,24.7) 34.794,24.7 cw(c36.1,24.7) 36.1,26.006 cw(c36.1,24.7) 37.406,24.7 cw(c36.1,24.7)
  pour cut-out: 46.2,27.834 cw(c46.2,29.14) 44.894,29.14 cw(c46.2,29.14) 46.2,30.446 cw(c46.2,29.14) 47.506,29.14 cw(c46.2,29.14)
  pour cut-out: 48.74,25.294 cw(c48.74,26.6) 47.434,26.6 cw(c48.74,26.6) 48.74,27.906 cw(c48.74,26.6) 50.046,26.6 cw(c48.74,26.6)
  pour cut-out: 64.181,26.4 ccw(c65.95,26.4) 65.95,24.631 ccw(c65.95,26.4) 67.719,26.4 ccw(c65.95,26.4) 65.95,28.169 ccw(c65.95,26.4)
  pour cut-out: 53.281,26.4 ccw(c55.05,26.4) 55.05,24.631 ccw(c55.05,26.4) 56.819,26.4 ccw(c55.05,26.4) 55.05,28.169 ccw(c55.05,26.4)
  pour cut-out: 82.54,65.78 87.04,65.78 87.04,60.08 82.54,60.08
  pour cut-out: 82.517,53.56 87.017,53.56 87.017,47.86 82.517,47.86
  pour cut-out: 134.08,28.76 139.774,34.454 140.57,34.449 140.57,34.18 139.8,34.18 134.38,28.76
  pour cut-out: 142.56,36.96 151.474,45.874 158.92,45.826 158.92,45.599 151.5,45.6 142.86,36.96
  pour cut-out: 77.5,54.4 77.8,54.1 77.8,49 77.4,48.6 76.3,48.6 75.9,49 75.9,54.1 76.2,54.4
  pour cut-out: 61,38.5 67.2,38.5 67.8,37.9 67.8,35.7 67.1,35 61.1,35 60.4,35.7 60.4,37.9
  pour cut-out: 44.05,10.1 44.05,9.7 82.7,9.7 84.3,8.1 84.661,8.701 83.262,10.1
  pour cut-out: 70.9,10.8 70.9,11.4 70.8,11.5 70.2,11.5 70.1,11.4 70.1,10.8 70.2,10.7 70.8,10.7

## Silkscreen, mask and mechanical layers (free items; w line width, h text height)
Top Overlay:
  text "Max comp height: 32mm" at 75.5,68.9 h0.76
  text "Width: 70mm" at 78,67.1 h0.76
  text "'.PRJ_Number' Rev.PCB_Rev" at 116.85,17.48 h4
  text "*" at 71.35,7.25 h2
  text "*" at 76.425,5.875 h2
  text ".Layer_Name" at -10.544,-45.406 h1.52
Bottom Overlay:
  text ".Layer_Name" at -10.544,-45.406 h1.52
Top Paste:
  text ".Layer_Name" at -10.544,-45.406 h1.52
Bottom Paste:
  text ".Layer_Name" at -10.544,-45.406 h1.52
Top Solder:
  rectangle: 42.8,5.9 47.1,8
  rectangle: 44.05,1.1 47.1,5.4
  text ".Layer_Name" at -10.544,-45.406 h1.52
  text ".Layer_Name" at -10.544,-45.406 h1.52
Bottom Solder:
  text ".Layer_Name" at -10.544,-45.406 h1.52
Drill Guide:
  text ".Layer_Name" at -10.544,-45.406 h1.52
M1 Board Outline:
  the board outline again, w0.254
  text ".Layer_Name" at -10.544,-45.406 h1.52
M2 Board Dimensions:
  rectangle: -25.2,-30.585 -22.025,-27.41
  rectangle: -22.025,-33.76 -12.5,-30.585
  lines w0.178: -25.2,-30.585 0.2,-30.585 ; -22.025,-33.76 -22.025,-27.41 ; -18.85,-33.76 -18.85,-27.41 ; -12.5,-33.76 -12.5,-27.41 ; -6.15,-33.76 -6.15,-27.41 ; -25.2,-33.76 0.2,-33.76 0.2,-27.41 -25.2,-27.41 -25.2,-33.76
  lines w0.254: 0,0 0,30 7,30 7,70 152.5,70 152.5,65.2 ccw(c153.95,65.45) 154.2,64 159,64 159,6 154.2,6 ccw(c154.2,4.8) 153,4.8 153,0 0,0
  text "Place holder for fan" at -5.85,39.425 h2.29 r90
  text ".Layer_Name" at -10.544,-45.406 h1.52
M3 3D STEP Top:
  text ".Layer_Name" at -10.544,-45.406 h1.52
M4 3D STEP Bottom:
  text ".Layer_Name" at -10.544,-45.406 h1.52
M5 Assembly Top:
  lines w0.254: -32.617,-47.226 135.023,-47.226 ; -32.617,-42.062 135.074,-42.062 ; -32.617,-36.897 -32.617,-52.391 69.11,-52.391 135.074,-52.391 135.074,-36.897 -32.604,-36.897 -32.604,-52.391 7.414,-52.391 ; 29.994,-52.391 29.994,-36.897 ; 62.176,-42.062 62.176,-36.897 ; 83.512,-42.062 83.512,-36.897 ; 99.311,-52.556 99.311,-47.404
  text "COMPONENTS MARKED 'DNP' SHOULD NOT BE POPULATED." at 4.099,-31.69 h1.52
  text "ASSEMBLY VARIANT:" at 4.086,-34.624 h1.52
  text ".VariantName" at 30.401,-34.624 h1.52
  text "PCB VIEWED FROM TOP SIDE" at -31.004,-40.254 h1.52
  text "BOARD #:" at 31.899,-40.254 h1.52
  text ".PRJ_Number" at 45.755,-40.254 h1.52
  text "REV:" at 67.205,-40.254 h1.52
  text ".PCB_Rev" at 74.609,-40.254 h1.52
  text "SVN REV:" at 88.49,-40.254 h1.52
  text ".VersionControl_RevNumber" at 101.343,-40.254 h1.52
  text "TID #:" at 31.899,-45.419 h1.52
  text ".TID" at 45.755,-45.419 h1.52
  text "PLOT NAME =" at -31.004,-50.634 h1.52
  text ".plot_File_Name" at -10.544,-50.634 h1.52
  text "GENERATED    :" at 31.95,-50.634 h1.52
  text ".Print_Date" at 54.035,-50.634 h1.52
  text ".Print_Time" at 72.552,-50.634 h1.52
  text "TEXAS INSTRUMENTS" at 104.67,-50.634 h1.52
M6 Assembly Bottom:
  lines w0.254: -32.63,-42.074 135.061,-42.074 ; -32.579,-47.239 135.061,-47.239 ; 3.134,-52.569 3.134,-47.417 ; 18.932,-42.074 18.932,-36.91 ; 40.268,-42.074 40.268,-36.91 ; 72.45,-52.404 72.45,-36.91 ; 95.031,-52.404 135.049,-52.404 135.049,-36.91 -32.63,-36.91 -32.63,-52.404 33.334,-52.404 135.061,-52.404 135.061,-36.91
  text "COMPONENTS MARKED 'DNP' SHOULD NOT BE POPULATED." at 148.891,-31.577 h1.52
  text ".VariantName" at 103.273,-34.624 h1.52
  text "ASSEMBLY VARIANT:" at 129.664,-34.624 h1.52
  text ".VersionControl_RevNumber" at 1.102,-40.267 h1.52
  text "SVN REV:" at 13.954,-40.267 h1.52
  text ".PCB_Rev" at 27.835,-40.267 h1.52
  text "REV:" at 35.239,-40.267 h1.52
  text ".PRJ_Number" at 56.69,-40.267 h1.52
  text "BOARD #:" at 70.545,-40.267 h1.52
  text "PCB VIEWED FROM BOTTOM SIDE" at 133.448,-40.267 h1.52
  text ".TID" at 56.69,-45.431 h1.52
  text "TID #:" at 70.545,-45.431 h1.52
  text "TEXAS INSTRUMENTS" at -2.226,-50.647 h1.52
  text ".Print_Time" at 29.893,-50.647 h1.52
  text ".Print_Date" at 48.409,-50.647 h1.52
  text "GENERATED    :" at 70.494,-50.647 h1.52
  text ".plot_File_Name" at 112.989,-50.647 h1.52
  text "PLOT NAME =" at 133.448,-50.647 h1.52
M9 Title Sheet:
  drawing of 55 lines, arcs and shapes, not listed
  text "1" at -6.408,180.527 h1.78
  text "2" at 56.982,180.527 h1.78
  text "3" at 120.211,180.527 h1.78
  text "4" at 183.88,180.527 h1.78
  text "5" at 247.355,180.527 h1.78
  text "6" at 310.982,180.527 h1.78
  text "A" at -35.779,151.495 h1.78
  text "A" at 340.141,151.495 h1.78
  text "B" at 340.141,91.043 h1.78
  text "C" at 340.141,30.718 h1.78
  text "PROJECT TITLE:" at 262.925,-16.552 h1.14
  text "DESIGNED FOR:" at 262.925,-24.197 h1.14
  text ".PRJ_Customer" at 264.195,-27.753 h1.78
  text "D" at -35.779,-29.48 h1.78
  text "D" at 340.141,-29.48 h1.78
  text "FILE NAME:" at 262.925,-31.817 h1.14
  text ".PCB_File_Name_No_Path" at 264.195,-34.865 h1.78
  text "Texas Instruments (TI) and/or its licensors do not warrant the accuracy or completeness of this specification" at 136.7,-38.976 h1.14
  text "ENGINEER:" at 262.925,-39.183 h1.14
  text "LAYOUT BY:" at 301.152,-39.183 h1.14
  text "or any information contained therein. TI and/or its licensors do not warrant that this design will meet" at 135.557,-41.837 h1.14
  text ".PRJ_Engineer" at 264.195,-43.12 h1.78
  text ".PCB_Layout" at 302.435,-43.12 h1.78
  text "the specifications, will be suitable for your application or fit for any particular purpose, or will operate in" at 135.557,-44.699 h1.14
  text ".Layer_Name" at -10.544,-45.406 h1.52
  text "ALTIUM DESIGNER VERSION:" at 301.152,-47.057 h1.14
  text "an implementation. TI and/or its licensors do not warrant that the design is production worthy. You should" at 135.557,-47.561 h1.14
  text "completely validate and test your design implementation to confirm the system functionality for your application." at 136.7,-50.422 h1.14
  text ".print_Scale" at 264.195,-50.443 h1.78
  text ".Application_BuildNumber" at 302.435,-50.443 h1.78
  text "1" at -6.408,-55.693 h1.78
  text "2" at 56.982,-55.693 h1.78
  text "3" at 120.211,-55.693 h1.78
  text "4" at 183.88,-55.693 h1.78
  text "5" at 247.355,-55.693 h1.78
  text "6" at 310.982,-55.693 h1.78
M10 Fab Notes:
  text ".Layer_Name" at -10.544,-45.406 h1.52
M11 Gerber Information:
  lines w0.254: -32.617,-47.226 135.023,-47.226 ; -32.617,-42.062 135.074,-42.062 ; -32.617,-36.897 -32.617,-52.391 69.11,-52.391 135.074,-52.391 135.074,-36.897 -32.604,-36.897 -32.604,-52.391 7.414,-52.391 ; 29.994,-52.391 29.994,-36.897 ; 62.176,-42.062 62.176,-36.897 ; 83.512,-42.062 83.512,-36.897 ; 99.311,-52.556 99.311,-47.404
  text "ALL ARTWORK VIEWED FROM TOP SIDE" at -31.004,-40.254 h1.52
  text "BOARD #:" at 31.899,-40.254 h1.52
  text ".PRJ_Number" at 45.755,-40.254 h1.52
  text "REV:" at 67.205,-40.254 h1.52
  text ".PCB_Rev" at 74.609,-40.254 h1.52
  text "SVN REV:" at 88.49,-40.254 h1.52
  text ".VersionControl_RevNumber" at 101.343,-40.254 h1.52
  text "LAYER NAME =" at -31.004,-45.406 h1.52
  text "TID #:" at 31.899,-45.419 h1.52
  text ".TID" at 45.755,-45.419 h1.52
  text "PLOT NAME =" at -31.004,-50.634 h1.52
  text ".plot_File_Name" at -10.544,-50.634 h1.52
  text "GENERATED    :" at 31.95,-50.634 h1.52
  text ".Print_Date" at 54.035,-50.634 h1.52
  text ".Print_Time" at 72.552,-50.634 h1.52
  text "TEXAS INSTRUMENTS" at 104.67,-50.634 h1.52
M12 Stackup:
  text ".Layer_Name" at -10.544,-45.406 h1.52
M13 Component Bodies Top:
  text ".Layer_Name" at -10.544,-45.406 h1.52
M14 Component Bodies Bottom:
  text ".Layer_Name" at -10.544,-45.406 h1.52
M15 Courtyards Top:
  text ".Layer_Name" at -10.544,-45.406 h1.52
M16 Courtyards Bottom:
  text ".Layer_Name" at -10.544,-45.406 h1.52
Drill Drawing:
  text ".Layer_Name" at -10.544,-45.406 h1.52
M17 Embedded Cavity:
  text ".Layer_Name" at -10.544,-45.406 h1.52
M18 Embedded Assembly:
  text ".Layer_Name" at -10.544,-45.406 h1.52
M19 Embedded Keepout:
  text ".Layer_Name" at -10.544,-45.406 h1.52

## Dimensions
5.8,70 to -0.5,30 on M2 Board Dimensions
159,70.133 to 7,70 on M2 Board Dimensions
159,-0.7 to 0,-0.1 on M2 Board Dimensions
7,87.8 to -26,69.1 on M2 Board Dimensions
-25.2,-33.76 to 0.2,-33.76 on M2 Board Dimensions
161.4,0 to 159,70 on M2 Board Dimensions
161,87.134 to -24,96.134 on M2 Board Dimensions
